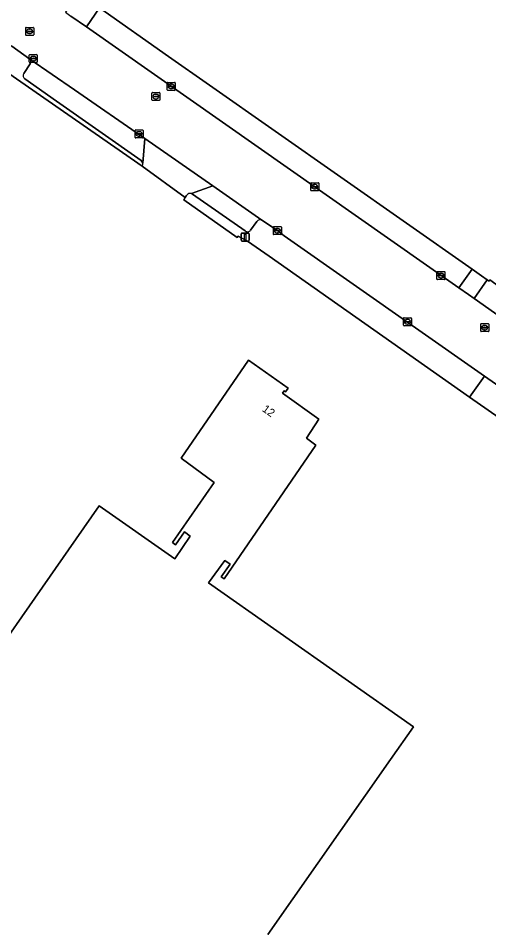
# Model space of a CAD drawing. Extents: x 155018 to 156648, y 383979 to 385733.
# Drawn here: x 155260.7 to 155319.4, y 385033.8 to 385148 of the extents above; entities that cross this region are included whole.
import ezdxf

# ---------------------------------------------------------------- set-up
doc = ezdxf.new("R2010")
doc.units = 0
for name, color, linetype in [('IMGEO_Erf', 7, 'Continuous'), ('IMGEO_Hek', 7, 'Continuous'), ('IMGEO_Kolk', 7, 'Continuous'), ('IMGEO_Lichtmast', 7, 'Continuous'), ('IMGEO_Pand', 7, 'Continuous'), ('IMGEO_Pand_nummerreeks', 7, 'Continuous'), ('IMGEO_Parkeervlak_open', 7, 'Continuous'), ('IMGEO_Rijbaan_lokaal_gesloten', 7, 'Continuous'), ('IMGEO_Rijbaan_lokaal_open', 7, 'Continuous'), ('IMGEO_Rioolput', 7, 'Continuous'), ('IMGEO_Voetpad_open', 7, 'Continuous')]:
    doc.layers.add(name, color=color, linetype=linetype)

msp = doc.modelspace()

# ---------------------------------------------------------------- linework, layer by layer
at = {"layer": 'IMGEO_Erf'}
for points in [[(155421.75, 385027.62), (155395, 385046.28), (155391.03, 385049.05), (155385.59, 385052.84), (155385.4, 385052.96), (155380.15, 385056.63), (155341.35, 385083.76), (155335.66, 385087.64), (155324.96, 385095.15), (155317.04, 385100.72), (155292, 385118.3), (155289.29, 385120.2), (155288.53, 385120.61), (155288.14, 385120.83), (155288.02, 385120.66), (155281.33, 385125.34), (155281.52, 385125.64), (155276.13, 385129.55), (155243.35, 385152.36), (155212.56, 385173.84)], [(155270.84, 385149.33), (155279.45, 385143.26), (155284.56, 385139.65), (155317.35, 385116.7), (155318.53, 385115.87), (155319.24, 385115.37), (155319.46, 385115.21), (155319.58, 385115.36), (155326.19, 385110.55), (155330.68, 385107.6), (155331.41, 385107.09), (155337.34, 385102.95), (155357.01, 385089.19), (155362.77, 385085.18), (155368.94, 385080.86), (155374.5, 385076.98), (155374.69, 385076.84), (155377.55, 385080.91), (155381.07, 385078.44), (155379.97, 385076.65), (155379.05, 385073.83), (155378.3, 385071.51)], [(155252.68, 385061.18), (155267.91, 385083.02), (155270.77, 385087.12), (155280.21, 385080.5), (155282.15, 385083.34), (155281.43, 385083.9), (155280.32, 385082.26), (155279.94, 385082.56), (155285.15, 385090.06), (155281.03, 385093.08), (155289.41, 385105.32), (155294.36, 385101.84), (155294.05, 385101.35), (155293.86, 385101.49), (155293.66, 385101.19), (155298.22, 385097.96), (155296.65, 385095.58), (155297.85, 385094.72), (155286.38, 385078), (155286, 385078.27), (155287.12, 385079.85), (155286.45, 385080.31), (155284.45, 385077.53), (155310.02, 385059.52), (155307.14, 385055.43), (155291.83, 385033.6)]]:
    msp.add_lwpolyline(points, dxfattribs=at)
at = {"layer": 'IMGEO_Hek'}
for points in [[(155288.02, 385120.66), (155288.14, 385120.83)], [(155288.53, 385120.61), (155288.14, 385120.83)], [(155289.29, 385120.2), (155288.53, 385120.61)]]:
    msp.add_lwpolyline(points, dxfattribs=at)
at = {"layer": 'IMGEO_Kolk'}
for p, q in [((155262.05, 385142.57), (155262.05, 385143.42)), ((155262.12, 385143.5), (155262.98, 385143.5)), ((155262.31, 385142.99), (155262.31, 385143)), ((155262.35, 385143.04), (155262.75, 385143.04)), ((155262.75, 385142.95), (155262.35, 385142.95)), ((155262.54, 385143.27), (155262.56, 385143.27)), ((155262.56, 385142.72), (155262.54, 385142.72)), ((155262.79, 385143), (155262.79, 385142.99)), ((155263.05, 385143.42), (155263.05, 385142.57)), ((155262.98, 385142.49), (155262.12, 385142.49)), ((155279.28, 385139.09), (155279.28, 385139.95)), ((155279.35, 385140.02), (155280.2, 385140.02)), ((155279.54, 385139.51), (155279.54, 385139.53)), ((155279.58, 385139.56), (155279.98, 385139.56)), ((155279.97, 385139.48), (155279.58, 385139.48)), ((155279.79, 385139.24), (155279.76, 385139.24)), ((155279.77, 385139.8), (155279.79, 385139.8)), ((155280.02, 385139.53), (155280.02, 385139.51)), ((155280.28, 385139.95), (155280.28, 385139.09)), ((155280.2, 385139.02), (155279.35, 385139.02)), ((155275.26, 385133.15), (155275.26, 385134)), ((155275.34, 385134.08), (155276.19, 385134.08)), ((155275.52, 385133.57), (155275.52, 385133.58)), ((155275.56, 385133.62), (155275.96, 385133.62)), ((155275.96, 385133.53), (155275.56, 385133.53)), ((155275.75, 385133.86), (155275.77, 385133.86)), ((155276, 385133.58), (155276, 385133.57)), ((155276.26, 385134), (155276.26, 385133.15)), ((155276.19, 385133.08), (155275.34, 385133.08)), ((155275.77, 385133.3), (155275.75, 385133.3)), ((155297.19, 385126.56), (155297.19, 385127.41)), ((155297.27, 385127.49), (155298.12, 385127.49)), ((155297.45, 385126.98), (155297.45, 385126.99)), ((155297.49, 385127.03), (155297.89, 385127.03)), ((155297.89, 385126.94), (155297.49, 385126.94)), ((155297.68, 385127.27), (155297.7, 385127.27)), ((155297.7, 385126.71), (155297.68, 385126.71)), ((155297.93, 385126.99), (155297.93, 385126.98)), ((155298.19, 385127.41), (155298.19, 385126.56)), ((155298.12, 385126.49), (155297.27, 385126.49)), ((155292.53, 385121.08), (155292.53, 385121.93)), ((155292.6, 385122), (155293.45, 385122)), ((155293.45, 385121), (155292.6, 385121)), ((155292.79, 385121.5), (155292.79, 385121.51)), ((155292.83, 385121.55), (155293.23, 385121.55)), ((155293.22, 385121.46), (155292.83, 385121.46)), ((155293.04, 385121.22), (155293.01, 385121.22)), ((155293.02, 385121.78), (155293.04, 385121.78)), ((155293.27, 385121.51), (155293.27, 385121.5)), ((155293.53, 385121.93), (155293.53, 385121.08)), ((155313.04, 385116.39), (155313.89, 385116.39)), ((155312.96, 385115.46), (155312.96, 385116.31)), ((155313.89, 385115.39), (155313.04, 385115.39)), ((155313.22, 385115.88), (155313.22, 385115.89)), ((155313.66, 385115.84), (155313.26, 385115.84)), ((155313.27, 385115.93), (155313.66, 385115.93)), ((155313.45, 385116.17), (155313.48, 385116.17)), ((155313.47, 385115.61), (155313.45, 385115.61)), ((155313.71, 385115.89), (155313.71, 385115.88)), ((155313.96, 385116.31), (155313.96, 385115.46)), ((155308.78, 385109.69), (155308.78, 385110.54)), ((155308.85, 385110.62), (155309.7, 385110.62)), ((155309.7, 385109.62), (155308.85, 385109.62)), ((155309.03, 385110.11), (155309.03, 385110.12)), ((155309.47, 385110.07), (155309.07, 385110.07)), ((155309.08, 385110.16), (155309.48, 385110.16)), ((155309.26, 385110.4), (155309.29, 385110.4)), ((155309.29, 385109.84), (155309.26, 385109.84)), ((155309.52, 385110.12), (155309.52, 385110.11)), ((155309.78, 385110.54), (155309.78, 385109.69))]:
    msp.add_line(p, q, dxfattribs=at)
for points in [[(155262.05, 385142.57), (155262.05, 385143.42)], [(155262.12, 385143.5), (155262.98, 385143.5)], [(155263.05, 385143.42), (155263.05, 385142.57)], [(155262.98, 385142.49), (155262.12, 385142.49)], [(155279.28, 385139.09), (155279.28, 385139.95)], [(155279.35, 385140.02), (155280.2, 385140.02)], [(155280.28, 385139.95), (155280.28, 385139.09)], [(155280.2, 385139.02), (155279.35, 385139.02)], [(155275.26, 385133.15), (155275.26, 385134)], [(155275.34, 385134.08), (155276.19, 385134.08)], [(155276.26, 385134), (155276.26, 385133.15)], [(155276.19, 385133.08), (155275.34, 385133.08)], [(155297.19, 385126.56), (155297.19, 385127.41)], [(155297.27, 385127.49), (155298.12, 385127.49)], [(155298.19, 385127.41), (155298.19, 385126.56)], [(155298.12, 385126.49), (155297.27, 385126.49)], [(155292.53, 385121.08), (155292.53, 385121.93)], [(155292.6, 385122), (155293.45, 385122)], [(155293.45, 385121), (155292.6, 385121)], [(155293.53, 385121.93), (155293.53, 385121.08)], [(155313.04, 385116.39), (155313.89, 385116.39)], [(155312.96, 385115.46), (155312.96, 385116.31)], [(155313.89, 385115.39), (155313.04, 385115.39)], [(155313.96, 385116.31), (155313.96, 385115.46)], [(155308.78, 385109.69), (155308.78, 385110.54)], [(155308.85, 385110.62), (155309.7, 385110.62)], [(155309.7, 385109.62), (155308.85, 385109.62)], [(155309.78, 385110.54), (155309.78, 385109.69)]]:
    msp.add_lwpolyline(points, dxfattribs=at)
for centre, radius, start, end in [((155262.13, 385143.42), 0.0765, 91.552, 178.448), ((155262.13, 385143.42), 0.0765, 91.552, 178.448), ((155262.35, 385143), 0.0403, 85.8775, 175.7526), ((155262.35, 385142.99), 0.0366, 178.938, 274.7102), ((155262.75, 385143), 0.0386, 1.7309, 96.639), ((155262.75, 385142.99), 0.043, 264.8664, 352.4533), ((155262.97, 385143.42), 0.0765, 1.552, 88.448), ((155262.97, 385143.42), 0.0765, 1.552, 88.448), ((155262.13, 385142.57), 0.0765, 181.552, 268.448), ((155262.13, 385142.57), 0.0765, 181.552, 268.448), ((155262.97, 385142.57), 0.0765, 271.552, 358.448), ((155262.97, 385142.57), 0.0765, 271.552, 358.448), ((155279.35, 385139.94), 0.0765, 91.552, 178.448), ((155279.35, 385139.94), 0.0765, 91.552, 178.448), ((155279.58, 385139.52), 0.0403, 85.8775, 175.7526), ((155279.57, 385139.51), 0.0366, 178.938, 274.7102), ((155279.98, 385139.52), 0.043, 264.8664, 352.4533), ((155279.98, 385139.52), 0.0386, 1.7309, 96.639), ((155280.2, 385139.94), 0.0765, 1.552, 88.448), ((155280.2, 385139.94), 0.0765, 1.552, 88.448), ((155279.35, 385139.09), 0.0765, 181.552, 268.448), ((155279.35, 385139.09), 0.0765, 181.552, 268.448), ((155280.2, 385139.09), 0.0765, 271.552, 358.448), ((155280.2, 385139.09), 0.0765, 271.552, 358.448), ((155275.34, 385134), 0.0765, 91.552, 178.448), ((155275.34, 385134), 0.0765, 91.552, 178.448), ((155275.56, 385133.58), 0.0403, 85.8775, 175.7526), ((155275.56, 385133.57), 0.0366, 178.938, 274.7102), ((155275.97, 385133.58), 0.0386, 1.7309, 96.639), ((155275.96, 385133.58), 0.043, 264.8664, 352.4533), ((155276.19, 385134), 0.0765, 1.552, 88.448), ((155276.19, 385134), 0.0765, 1.552, 88.448), ((155275.34, 385133.15), 0.0765, 181.552, 268.448), ((155275.34, 385133.15), 0.0765, 181.552, 268.448), ((155276.19, 385133.15), 0.0765, 271.552, 358.448), ((155276.19, 385133.15), 0.0765, 271.552, 358.448), ((155297.27, 385127.41), 0.0765, 91.552, 178.448), ((155297.27, 385127.41), 0.0765, 91.552, 178.448), ((155297.49, 385126.99), 0.0403, 85.8775, 175.7526), ((155297.49, 385126.98), 0.0366, 178.938, 274.7102), ((155297.9, 385126.99), 0.0386, 1.7309, 96.639), ((155297.89, 385126.99), 0.043, 264.8664, 352.4533), ((155298.12, 385127.41), 0.0765, 1.552, 88.448), ((155298.12, 385127.41), 0.0765, 1.552, 88.448), ((155297.27, 385126.56), 0.0765, 181.552, 268.448), ((155297.27, 385126.56), 0.0765, 181.552, 268.448), ((155298.12, 385126.56), 0.0765, 271.552, 358.448), ((155298.12, 385126.56), 0.0765, 271.552, 358.448), ((155292.6, 385121.93), 0.0765, 91.552, 178.448), ((155292.6, 385121.93), 0.0765, 91.552, 178.448), ((155292.6, 385121.08), 0.0765, 181.552, 268.448), ((155292.6, 385121.08), 0.0765, 181.552, 268.448), ((155292.83, 385121.51), 0.0403, 85.8775, 175.7526), ((155292.82, 385121.5), 0.0366, 178.938, 274.7102), ((155293.23, 385121.5), 0.043, 264.8664, 352.4533), ((155293.23, 385121.51), 0.0386, 1.7309, 96.639), ((155293.45, 385121.93), 0.0765, 1.552, 88.448), ((155293.45, 385121.93), 0.0765, 1.552, 88.448), ((155293.45, 385121.08), 0.0765, 271.552, 358.448), ((155293.45, 385121.08), 0.0765, 271.552, 358.448), ((155313.04, 385116.31), 0.0765, 91.552, 178.448), ((155313.04, 385116.31), 0.0765, 91.552, 178.448), ((155313.89, 385116.31), 0.0765, 1.552, 88.448), ((155313.89, 385116.31), 0.0765, 1.552, 88.448), ((155313.04, 385115.46), 0.0765, 181.552, 268.448), ((155313.04, 385115.46), 0.0765, 181.552, 268.448), ((155313.26, 385115.89), 0.0403, 85.8775, 175.7526), ((155313.26, 385115.88), 0.0366, 178.938, 274.7102), ((155313.67, 385115.89), 0.0386, 1.7309, 96.639), ((155313.66, 385115.89), 0.043, 264.8664, 352.4533), ((155313.89, 385115.46), 0.0765, 271.552, 358.448), ((155313.89, 385115.46), 0.0765, 271.552, 358.448), ((155308.85, 385110.54), 0.0765, 91.552, 178.448), ((155308.85, 385110.54), 0.0765, 91.552, 178.448), ((155308.85, 385109.69), 0.0765, 181.552, 268.448), ((155308.85, 385109.69), 0.0765, 181.552, 268.448), ((155309.08, 385110.12), 0.0403, 85.8775, 175.7526), ((155309.07, 385110.11), 0.0366, 178.938, 274.7102), ((155309.48, 385110.12), 0.043, 264.8664, 352.4533), ((155309.48, 385110.12), 0.0386, 1.7309, 96.639), ((155309.7, 385110.54), 0.0765, 1.552, 88.448), ((155309.7, 385110.54), 0.0765, 1.552, 88.448), ((155309.7, 385109.69), 0.0765, 271.552, 358.448), ((155309.7, 385109.69), 0.0765, 271.552, 358.448)]:
    msp.add_arc(centre, radius, start, end, dxfattribs=at)
for centre, major_axis, ratio, start_param, end_param in [((155262.54, 385142.99), (-0.387, 0.002), 0.722429, 4.712389, 7.853982), ((155262.56, 385142.99), (-0.39, 0.002), 0.717154, 1.570796, 4.712389), ((155279.76, 385139.52), (-0.387, 0.002), 0.722429, 4.712389, 7.853982), ((155279.79, 385139.52), (-0.39, 0.002), 0.717154, 1.570796, 4.712389), ((155275.75, 385133.58), (-0.387, 0.002), 0.722429, 4.712389, 7.853982), ((155275.77, 385133.58), (-0.39, 0.002), 0.717154, 1.570796, 4.712389), ((155297.68, 385126.99), (-0.387, 0.002), 0.722429, 4.712389, 7.853982), ((155297.7, 385126.99), (-0.39, 0.002), 0.717154, 1.570796, 4.712389), ((155293.01, 385121.5), (-0.387, 0.002), 0.722429, 4.712389, 7.853982), ((155293.04, 385121.5), (-0.39, 0.002), 0.717154, 1.570796, 4.712389), ((155313.45, 385115.89), (-0.387, 0.002), 0.722429, 4.712389, 7.853982), ((155313.47, 385115.89), (-0.39, 0.002), 0.717154, 1.570796, 4.712389), ((155309.26, 385110.12), (-0.387, 0.002), 0.722429, 4.712389, 7.853982), ((155309.29, 385110.12), (-0.39, 0.002), 0.717154, 1.570796, 4.712389)]:
    msp.add_ellipse(centre, major_axis=major_axis, ratio=ratio, start_param=start_param, end_param=end_param, dxfattribs=at)
at = {"layer": 'IMGEO_Lichtmast'}
for p, q in [((155288.51, 385120.3), (155288.51, 385121.1)), ((155288.51, 385121.1), (155288.51, 385120.3)), ((155288.61, 385121.2), (155289.4, 385121.2)), ((155289.4, 385121.2), (155288.61, 385121.2)), ((155289.5, 385121.1), (155289.5, 385120.3)), ((155289.5, 385120.3), (155289.5, 385121.1)), ((155289.4, 385120.2), (155288.61, 385120.2)), ((155288.61, 385120.2), (155289.4, 385120.2))]:
    msp.add_line(p, q, dxfattribs=at)
msp.add_lwpolyline([(155288.93, 385121.08), (155289.08, 385121.08), (155289.08, 385120.33), (155288.93, 385120.33), (155288.93, 385121.08)], dxfattribs=at)
for centre, start, end in [((155288.61, 385121.1), 90, 180), ((155288.61, 385121.1), 90, 180), ((155289.4, 385121.1), 0, 90), ((155289.4, 385121.1), 360, 90), ((155288.61, 385120.3), 180, 270), ((155288.61, 385120.3), 180, 270), ((155289.4, 385120.3), 270, 0), ((155289.4, 385120.3), 270, 0)]:
    msp.add_arc(centre, 0.1, start, end, dxfattribs=at)
at = {"layer": 'IMGEO_Pand'}
msp.add_lwpolyline([(155291.83, 385033.6), (155307.14, 385055.43), (155310.02, 385059.52), (155284.45, 385077.53), (155286.45, 385080.31), (155287.12, 385079.85), (155286, 385078.27), (155286.38, 385078), (155297.85, 385094.72), (155296.65, 385095.58), (155298.22, 385097.96), (155293.66, 385101.19), (155293.86, 385101.49), (155294.05, 385101.35), (155294.36, 385101.84), (155289.41, 385105.32), (155281.03, 385093.08), (155285.15, 385090.06), (155279.94, 385082.56), (155280.32, 385082.26), (155281.43, 385083.9), (155282.15, 385083.34), (155280.21, 385080.5), (155270.77, 385087.12), (155267.91, 385083.02), (155252.68, 385061.18)], dxfattribs=at)
at = {"layer": 'IMGEO_Parkeervlak_open'}
msp.add_lwpolyline([(155284.56, 385139.65), (155279.45, 385143.26), (155270.84, 385149.33), (155269.21, 385146.94), (155315.7, 385114.36), (155317.35, 385116.7)], close=True, dxfattribs=at)
for points in [[(155261.51, 385140.44), (155265.45, 385137.68), (155276.03, 385130.27), (155276.23, 385129.93), (155276.49, 385133.02), (155267.69, 385139.07), (155262.14, 385142.93)], [(155262.17, 385142.32), (155261.39, 385141.14)], [(155284.97, 385127.1), (155282.31, 385126.12), (155282.45, 385126.07), (155289, 385121.46)], [(155291.11, 385122.81), (155284.97, 385127.1)], [(155289.69, 385121.55), (155290.47, 385122.65)]]:
    msp.add_lwpolyline(points, dxfattribs=at)
for centre, radius, start, end in [((155261.77, 385142.61), 0.493, 325.0816, 40.9738), ((155261.79, 385140.85), 0.497, 144.7526, 235.8715), ((155290.88, 385122.39), 0.483, 60.673, 146.9791), ((155289.3, 385121.85), 0.491, 232.3201, 322.8474)]:
    msp.add_arc(centre, radius, start, end, dxfattribs=at)
at = {"layer": 'IMGEO_Rijbaan_lokaal_gesloten'}
for points in [[(155254.18, 385148.52), (155259.89, 385144.52), (155262.14, 385142.93), (155267.69, 385139.07), (155276.49, 385133.02), (155284.97, 385127.1), (155291.11, 385122.81), (155293.03, 385121.5), (155293.87, 385120.84), (155318.91, 385103.34), (155326.85, 385097.79), (155337.53, 385090.32), (155343.17, 385086.38), (155381.97, 385059.23), (155386.95, 385055.78), (155387.45, 385055.41), (155392.86, 385051.63), (155396.82, 385048.86), (155422.08, 385031.23)], [(155426.08, 385037.13), (155420.14, 385041.29), (155419.86, 385041.58), (155414.44, 385045.35), (155378.61, 385070.28), (155373.16, 385074.07), (155371.07, 385075.54), (155365.02, 385079.79), (155362.62, 385081.43), (155361.07, 385082.55), (155355.21, 385086.68), (155344.84, 385093.91), (155335.61, 385100.39), (155329.74, 385104.51), (155329.67, 385104.56), (155324.53, 385108.17), (155317.59, 385113.03), (155316.9, 385113.52), (155315.7, 385114.36), (155269.21, 385146.94), (155267.26, 385148.3)]]:
    msp.add_lwpolyline(points, dxfattribs=at)
at = {"layer": 'IMGEO_Rijbaan_lokaal_open'}
for points in [[(155276.49, 385133.02), (155276.23, 385129.93)], [(155282.31, 385126.12), (155284.97, 385127.1), (155276.49, 385133.02)], [(155276.13, 385129.55), (155281.52, 385125.64), (155281.66, 385125.85), (155281.73, 385125.94)]]:
    msp.add_lwpolyline(points, dxfattribs=at)
for points in [[(155319.58, 385115.36), (155319.46, 385115.21), (155319.24, 385115.37), (155317.59, 385113.03), (155324.53, 385108.17), (155325.91, 385110.21), (155326.19, 385110.55)], [(155318.91, 385103.34), (155317.04, 385100.72), (155324.96, 385095.15), (155326.85, 385097.79)]]:
    msp.add_lwpolyline(points, close=True, dxfattribs=at)
for centre, radius, start, end in [((155275.87, 385129.81), 0.376, 314.7173, 18.0543), ((155282.13, 385125.65), 0.5, 69.6477, 144.5993)]:
    msp.add_arc(centre, radius, start, end, dxfattribs=at)
at = {"layer": 'IMGEO_Rioolput'}
for p, q in [((155261.6, 385145.96), (155261.6, 385146.81)), ((155261.67, 385146.89), (155262.52, 385146.89)), ((155261.85, 385146.38), (155261.85, 385146.39)), ((155262.29, 385146.34), (155261.89, 385146.34)), ((155261.9, 385146.43), (155262.29, 385146.43)), ((155262.08, 385146.67), (155262.11, 385146.67)), ((155262.11, 385146.11), (155262.08, 385146.11)), ((155262.34, 385146.39), (155262.34, 385146.38)), ((155262.6, 385146.81), (155262.6, 385145.96)), ((155262.52, 385145.89), (155261.67, 385145.89)), ((155277.36, 385137.83), (155277.36, 385138.68)), ((155277.44, 385138.75), (155278.29, 385138.75)), ((155277.62, 385138.25), (155277.62, 385138.26)), ((155278.06, 385138.21), (155277.66, 385138.21)), ((155277.67, 385138.3), (155278.06, 385138.3)), ((155277.85, 385138.53), (155277.88, 385138.53)), ((155278.11, 385138.26), (155278.11, 385138.25)), ((155278.36, 385138.68), (155278.36, 385137.83)), ((155278.29, 385137.75), (155277.44, 385137.75)), ((155277.87, 385137.97), (155277.85, 385137.97)), ((155318.42, 385108.96), (155318.42, 385109.81)), ((155318.49, 385109.89), (155319.35, 385109.89)), ((155318.91, 385109.67), (155318.93, 385109.67)), ((155319.42, 385109.81), (155319.42, 385108.96)), ((155319.35, 385108.89), (155318.49, 385108.89)), ((155318.68, 385109.38), (155318.68, 385109.39)), ((155318.72, 385109.43), (155319.12, 385109.43)), ((155319.12, 385109.34), (155318.72, 385109.34)), ((155318.93, 385109.11), (155318.9, 385109.11)), ((155319.16, 385109.39), (155319.16, 385109.38))]:
    msp.add_line(p, q, dxfattribs=at)
for points in [[(155261.6, 385145.96), (155261.6, 385146.81)], [(155261.67, 385146.89), (155262.52, 385146.89)], [(155262.6, 385146.81), (155262.6, 385145.96)], [(155262.52, 385145.89), (155261.67, 385145.89)], [(155277.36, 385137.83), (155277.36, 385138.68)], [(155277.44, 385138.75), (155278.29, 385138.75)], [(155278.36, 385138.68), (155278.36, 385137.83)], [(155278.29, 385137.75), (155277.44, 385137.75)], [(155318.42, 385108.96), (155318.42, 385109.81)], [(155318.49, 385109.89), (155319.35, 385109.89)], [(155319.42, 385109.81), (155319.42, 385108.96)], [(155319.35, 385108.89), (155318.49, 385108.89)]]:
    msp.add_lwpolyline(points, dxfattribs=at)
for centre, radius, start, end in [((155261.67, 385146.81), 0.0765, 91.552, 178.448), ((155261.67, 385146.81), 0.0765, 91.552, 178.448), ((155261.89, 385146.39), 0.0403, 85.8775, 175.7526), ((155261.89, 385146.38), 0.0366, 178.938, 274.7102), ((155262.3, 385146.39), 0.0386, 1.7309, 96.639), ((155262.3, 385146.39), 0.043, 264.8664, 352.4533), ((155262.52, 385146.81), 0.0765, 1.552, 88.448), ((155262.52, 385146.81), 0.0765, 1.552, 88.448), ((155261.67, 385145.96), 0.0765, 181.552, 268.448), ((155261.67, 385145.96), 0.0765, 181.552, 268.448), ((155262.52, 385145.96), 0.0765, 271.552, 358.448), ((155262.52, 385145.96), 0.0765, 271.552, 358.448), ((155277.44, 385138.68), 0.0765, 91.552, 178.448), ((155277.44, 385138.68), 0.0765, 91.552, 178.448), ((155277.66, 385138.26), 0.0403, 85.8775, 175.7526), ((155277.66, 385138.25), 0.0366, 178.938, 274.7102), ((155278.07, 385138.26), 0.0386, 1.7309, 96.639), ((155278.06, 385138.25), 0.043, 264.8664, 352.4533), ((155278.29, 385138.68), 0.0765, 1.552, 88.448), ((155278.29, 385138.68), 0.0765, 1.552, 88.448), ((155277.44, 385137.83), 0.0765, 181.552, 268.448), ((155277.44, 385137.83), 0.0765, 181.552, 268.448), ((155278.29, 385137.83), 0.0765, 271.552, 358.448), ((155278.29, 385137.83), 0.0765, 271.552, 358.448), ((155318.5, 385109.81), 0.0765, 91.552, 178.448), ((155318.5, 385109.81), 0.0765, 91.552, 178.448), ((155319.34, 385109.81), 0.0765, 1.552, 88.448), ((155319.34, 385109.81), 0.0765, 1.552, 88.448), ((155318.5, 385108.96), 0.0765, 181.552, 268.448), ((155318.5, 385108.96), 0.0765, 181.552, 268.448), ((155318.72, 385109.39), 0.0403, 85.8775, 175.7526), ((155318.71, 385109.38), 0.0366, 178.938, 274.7102), ((155319.12, 385109.39), 0.0386, 1.7309, 96.639), ((155319.12, 385109.39), 0.043, 264.8664, 352.4533), ((155319.34, 385108.96), 0.0765, 271.552, 358.448), ((155319.34, 385108.96), 0.0765, 271.552, 358.448)]:
    msp.add_arc(centre, radius, start, end, dxfattribs=at)
for centre, major_axis, ratio, start_param, end_param in [((155262.08, 385146.39), (-0.387, 0.002), 0.722429, 4.712389, 7.853982), ((155262.11, 385146.39), (-0.39, 0.002), 0.717154, 1.570796, 4.712389), ((155277.85, 385138.25), (-0.387, 0.002), 0.722429, 4.712389, 7.853982), ((155277.87, 385138.25), (-0.39, 0.002), 0.717154, 1.570796, 4.712389), ((155318.91, 385109.39), (-0.387, 0.002), 0.722429, 4.712389, 7.853982), ((155318.93, 385109.39), (-0.39, 0.002), 0.717154, 1.570796, 4.712389)]:
    msp.add_ellipse(centre, major_axis=major_axis, ratio=ratio, start_param=start_param, end_param=end_param, dxfattribs=at)
at = {"layer": 'IMGEO_Voetpad_open'}
for points in [[(155212.56, 385173.84), (155243.35, 385152.36), (155276.13, 385129.55)], [(155262.14, 385142.93), (155259.89, 385144.52)], [(155261.39, 385141.14), (155262.17, 385142.32)], [(155276.23, 385129.93), (155276.03, 385130.27), (155265.45, 385137.68), (155261.51, 385140.44)], [(155281.73, 385125.94), (155281.66, 385125.85), (155281.52, 385125.64), (155281.33, 385125.34), (155288.02, 385120.66), (155288.14, 385120.83), (155288.53, 385120.61), (155289.29, 385120.2), (155292, 385118.3), (155317.04, 385100.72), (155318.91, 385103.34), (155293.87, 385120.84)], [(155289, 385121.46), (155282.45, 385126.07), (155282.31, 385126.12)], [(155290.47, 385122.65), (155289.69, 385121.55)], [(155293.87, 385120.84), (155293.03, 385121.5), (155291.11, 385122.81)]]:
    msp.add_lwpolyline(points, dxfattribs=at)
for points in [[(155270.84, 385149.33), (155268.92, 385150.68), (155268.25, 385151.15), (155266.57, 385148.78), (155267.26, 385148.3), (155269.21, 385146.94)], [(155319.24, 385115.37), (155318.53, 385115.87), (155317.35, 385116.7), (155315.7, 385114.36), (155316.9, 385113.52), (155317.59, 385113.03)]]:
    msp.add_lwpolyline(points, close=True, dxfattribs=at)
for centre, radius, start, end in [((155261.77, 385142.61), 0.493, 325.0816, 40.9738), ((155261.79, 385140.85), 0.497, 144.7526, 235.8715), ((155275.87, 385129.81), 0.376, 314.7173, 18.0543), ((155282.13, 385125.65), 0.5, 69.6477, 144.5993), ((155290.88, 385122.39), 0.483, 60.673, 146.9791), ((155289.3, 385121.85), 0.491, 232.3201, 322.8474)]:
    msp.add_arc(centre, radius, start, end, dxfattribs=at)

# ---------------------------------------------------------------- texts
at = {"layer": 'IMGEO_Pand_nummerreeks'}
msp.add_text('12', height=1, rotation=324.6686, dxfattribs=at).set_placement((155291.06, 385099.02))

doc.saveas('drawing.dxf')
